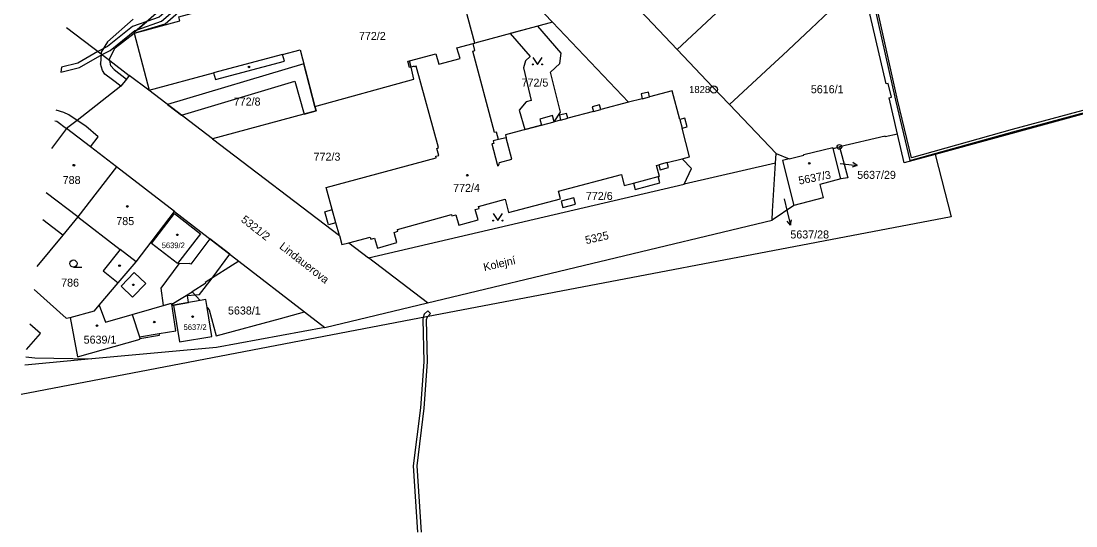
# Model space of a CAD drawing. Extents: x -821458 to -820266, y -1071458 to -1069826.
# Drawn here: x -821428.9 to -821204.8, y -1070135.7 to -1070028.3 of the extents above; entities that cross this region are included whole.
import ezdxf

# ---------------------------------------------------------------- set-up
doc = ezdxf.new("R2010")
doc.units = 0
for name, color, linetype in [('Vrstva 1', 7, 'Continuous'), ('Vrstva 13', 7, 'Continuous'), ('Vrstva 2', 7, 'Continuous'), ('Vrstva 3', 7, 'Continuous'), ('Vrstva 4', 7, 'Continuous'), ('Vrstva 5', 7, 'Continuous'), ('Vrstva 7', 7, 'Continuous'), ('Vrstva 8', 7, 'Continuous')]:
    doc.layers.add(name, color=color, linetype=linetype)

msp = doc.modelspace()

# ---------------------------------------------------------------- linework, layer by layer
at = {"layer": 'Vrstva 1'}
for p, q in [((-821332.49, -1070033), (-821340.69, -1070002.53)), ((-821340.69, -1070002.53), (-821315.99, -1070028.55)), ((-821299.98, -1070023.29), (-821289.45, -1070034.4)), ((-821315.99, -1070028.55), (-821332.49, -1070033)), ((-821299.81, -1070045.6), (-821315.99, -1070028.55)), ((-821404.89, -1070030.92), (-821401.66, -1070043)), ((-821332.84, -1070033.09), (-821332.49, -1070033)), ((-821401.77, -1070043.03), (-821405.9, -1070039.88)), ((-821182.41, -1070042.44), (-821234.69, -1070056.69)), ((-821401.77, -1070043.03), (-821401.66, -1070043)), ((-821388.21, -1070053.38), (-821401.77, -1070043.03)), ((-821268.48, -1070056.5), (-821278.33, -1070046.1)), ((-821388.21, -1070053.38), (-821361.25, -1070073.95)), ((-821256.32, -1070055.41), (-821255.01, -1070055.1)), ((-821254.68, -1070061.91), (-821256.32, -1070055.41)), ((-821268.6, -1070058.51), (-821288.01, -1070063.04)), ((-821268.6, -1070058.51), (-821268.48, -1070056.5)), ((-821268.48, -1070056.5), (-821265.69, -1070057.64)), ((-821408.59, -1070059.33), (-821416.81, -1070069.97)), ((-821396.32, -1070068.8), (-821408.59, -1070059.33)), ((-821355.07, -1070078.67), (-821288.01, -1070063.04)), ((-821396.32, -1070068.8), (-821382.59, -1070079.41)), ((-821264.67, -1070067.57), (-821269.3, -1070070.69)), ((-821416.81, -1070069.97), (-821420.03, -1070073.86)), ((-821342.51, -1070088.26), (-821269.3, -1070070.69)), ((-821420.03, -1070073.86), (-821425.52, -1070080.51)), ((-821359.25, -1070075.48), (-821355.07, -1070078.67)), ((-821342.51, -1070088.26), (-821355.07, -1070078.67)), ((-821382.59, -1070079.41), (-821368.64, -1070090.17)), ((-821392.56, -1070085.88), (-821390.82, -1070087.72)), ((-821364.34, -1070093.49), (-821342.51, -1070088.26)), ((-821368.64, -1070090.17), (-821364.34, -1070093.49))]:
    msp.add_line(p, q, dxfattribs=at)
for points in [[(-821355.04, -1069987.4), (-821361.05, -1069992.64), (-821400.19, -1070026.71), (-821404.92, -1070030.82), (-821404.89, -1070030.92)], [(-821404.89, -1070030.92), (-821402.96, -1070030.39), (-821395.18, -1070028.26), (-821395.4, -1070027.44), (-821385.84, -1070024.9), (-821385.62, -1070025.72), (-821378.18, -1070023.74), (-821378.43, -1070022.94), (-821376.42, -1070022.4), (-821376.21, -1070023.22), (-821371.58, -1070021.98), (-821371.8, -1070021.15), (-821367.67, -1070020.04), (-821369.02, -1070015.05), (-821366.37, -1070014.32), (-821356.12, -1070011.49), (-821354.5, -1070017.79), (-821352.33, -1070017.08), (-821352.03, -1070017.97), (-821351.61, -1070017.83), (-821357.55, -1069995.73), (-821357.82, -1069994.73), (-821358.41, -1069992.32), (-821352.01, -1069990.61)], [(-821289.45, -1070034.4), (-821279.09, -1070024.66), (-821277.81, -1070023.46), (-821265.53, -1070012.14)], [(-821278.33, -1070046.1), (-821268.7, -1070037.11), (-821267.06, -1070035.58), (-821261.06, -1070029.96), (-821258.36, -1070027.44), (-821249.59, -1070019.24)], [(-821242.69, -1070052.35), (-821244.41, -1070044.64), (-821243.95, -1070044.52), (-821244.63, -1070041.59), (-821245.07, -1070041.7), (-821249.48, -1070022.73), (-821248.91, -1070022.58), (-821249.59, -1070019.24)], [(-821419.24, -1070029.7), (-821411.87, -1070035.32), (-821410.92, -1070036.04), (-821410.03, -1070036.72), (-821405.9, -1070039.88)], [(-821346.01, -1070038.12), (-821346.35, -1070038.21), (-821346.71, -1070036.89), (-821346.33, -1070036.78), (-821340.76, -1070035.28), (-821340.11, -1070037.52), (-821335.6, -1070036.3), (-821336.27, -1070034.02), (-821332.84, -1070033.09)], [(-821299.81, -1070045.6), (-821305.72, -1070047.14), (-821305.98, -1070046.14), (-821307.53, -1070046.54), (-821307.27, -1070047.55), (-821312.7, -1070048.98), (-821312.96, -1070047.97), (-821314.5, -1070048.37), (-821314.24, -1070049.38), (-821315.61, -1070049.76), (-821315.97, -1070048.44), (-821318.67, -1070049.16), (-821318.31, -1070050.48), (-821325.96, -1070052.5), (-821325.79, -1070053.13), (-821327.43, -1070053.5), (-821327.84, -1070051.97), (-821328.26, -1070052.06), (-821332.89, -1070034.72), (-821332.49, -1070034.62), (-821332.84, -1070033.09)], [(-821401.66, -1070043), (-821387.99, -1070039.35), (-821387.61, -1070040.77), (-821372.94, -1070036.84), (-821373.32, -1070035.42), (-821369.59, -1070034.43), (-821366.45, -1070046.49)], [(-821289.45, -1070034.4), (-821281.88, -1070042.37), (-821278.5, -1070045.92), (-821278.33, -1070046.1)], [(-821366.45, -1070046.49), (-821345.41, -1070040.66), (-821346.01, -1070038.12)], [(-821361.25, -1070073.95), (-821362, -1070071.2), (-821363.6, -1070071.64), (-821364.36, -1070068.86), (-821362.76, -1070068.42), (-821364.05, -1070063.73), (-821340.69, -1070057.44), (-821340.79, -1070057.08), (-821340.15, -1070056.89), (-821340.56, -1070055.43), (-821340.17, -1070055.22), (-821344.92, -1070037.95), (-821345.35, -1070038.07), (-821345.38, -1070037.95), (-821346.01, -1070038.12)], [(-821405.9, -1070039.88), (-821406.52, -1070040.69), (-821407.66, -1070042.21), (-821416.96, -1070049.45), (-821419.2, -1070051.19)], [(-821288.44, -1070057.59), (-821286.83, -1070057.17), (-821288.43, -1070051.09), (-821287.35, -1070050.79), (-821287.83, -1070049), (-821288.9, -1070049.28), (-821290.51, -1070043.17), (-821295.34, -1070044.45), (-821295.6, -1070043.44), (-821297.15, -1070043.84), (-821296.89, -1070044.84), (-821299.81, -1070045.6)], [(-821366.45, -1070046.49), (-821366.21, -1070047.43), (-821388.21, -1070053.38)], [(-821419.2, -1070051.19), (-821422.42, -1070055.41)], [(-821408.59, -1070059.33), (-821414.1, -1070055.1), (-821419.2, -1070051.19)], [(-821242.69, -1070052.35), (-821245.27, -1070052.96), (-821245.31, -1070052.82), (-821255.01, -1070055.1)], [(-821234.69, -1070056.69), (-821241.23, -1070058.48), (-821242.69, -1070052.35)], [(-821265.69, -1070057.64), (-821262.54, -1070056.84), (-821262.57, -1070056.72), (-821256.38, -1070055.19), (-821256.32, -1070055.41)], [(-821255.01, -1070055.1), (-821253.21, -1070061.68), (-821254.68, -1070061.91)], [(-821234.69, -1070056.69), (-821231.29, -1070069.95), (-821344.25, -1070091.52), (-821428.88, -1070107.69)], [(-821359.25, -1070075.48), (-821354.71, -1070074.27), (-821354.59, -1070074.69), (-821353.76, -1070074.46), (-821353.18, -1070076.58), (-821349.04, -1070075.43), (-821349.64, -1070073.27), (-821348.8, -1070073.03), (-821348.91, -1070072.65), (-821337.42, -1070069.46), (-821337.34, -1070069.75), (-821336.48, -1070069.5), (-821335.89, -1070071.71), (-821331.76, -1070070.56), (-821332.37, -1070068.39), (-821331.58, -1070068.18), (-821331.69, -1070067.79), (-821326.04, -1070066.21), (-821325.31, -1070069), (-821314.25, -1070066.12), (-821314.67, -1070064.51), (-821301.34, -1070060.97), (-821300.74, -1070063.29), (-821298.74, -1070062.77), (-821298.41, -1070064.11), (-821293.14, -1070062.74), (-821293.49, -1070061.41), (-821293.25, -1070061.35), (-821293.88, -1070059.02), (-821293.36, -1070058.88), (-821293.08, -1070059.95), (-821291.3, -1070059.48), (-821291.58, -1070058.41), (-821288.44, -1070057.59)], [(-821288.01, -1070063.04), (-821286.46, -1070059.67), (-821288.44, -1070057.59)], [(-821269.3, -1070070.69), (-821269.19, -1070068.76), (-821268.6, -1070058.51)], [(-821265.69, -1070057.64), (-821267.13, -1070058), (-821264.67, -1070067.57)], [(-821254.68, -1070061.91), (-821259.17, -1070063.06), (-821258.49, -1070065.94), (-821264.67, -1070067.57)], [(-821408.29, -1070084.01), (-821404.46, -1070079.49), (-821396.32, -1070068.8)], [(-821390.78, -1070073.56), (-821395.65, -1070079.9), (-821401.2, -1070075.6), (-821396.29, -1070069.25), (-821390.78, -1070073.56)], [(-821420.03, -1070073.86), (-821424.29, -1070070.56)], [(-821416.81, -1070069.97), (-821407.84, -1070076.88), (-821411.44, -1070081.43), (-821408.29, -1070084.01)], [(-821361.25, -1070073.95), (-821360.73, -1070075.84), (-821359.25, -1070075.48)], [(-821382.59, -1070079.41), (-821389.77, -1070083.88), (-821389.64, -1070084.09), (-821392.56, -1070085.88)], [(-821426.13, -1070085.41), (-821419.3, -1070091.5), (-821418.49, -1070091.38)], [(-821418.49, -1070091.38), (-821413.3, -1070089.92), (-821412.27, -1070088.7), (-821408.29, -1070084.01)], [(-821418.49, -1070091.38), (-821416.93, -1070099.75), (-821403.58, -1070095.99), (-821403.65, -1070095.8), (-821399.49, -1070095.09), (-821399.55, -1070094.77), (-821395.97, -1070094.16), (-821396.86, -1070088.51), (-821392.56, -1070085.88)], [(-821389.37, -1070089.24), (-821389.66, -1070087.52), (-821390.82, -1070087.72)], [(-821390.82, -1070087.72), (-821396.53, -1070088.71), (-821395.25, -1070096.54), (-821388.35, -1070095.41), (-821389.37, -1070089.24)], [(-821389.37, -1070089.24), (-821388.9, -1070089.74), (-821387.42, -1070095.23), (-821373.76, -1070091.55), (-821368.64, -1070090.17)], [(-821427.7, -1070098.14), (-821424.78, -1070094.75), (-821427.04, -1070092.8)], [(-821364.34, -1070093.49), (-821387.38, -1070097.71), (-821413.86, -1070100.14)], [(-821413.86, -1070100.14), (-821428.12, -1070101.5)], [(-821427.9, -1070099.74), (-821425.97, -1070099.92), (-821413.86, -1070100.14)]]:
    msp.add_lwpolyline(points, dxfattribs=at)
at = {"layer": 'Vrstva 13'}
msp.add_line((-821420.29, -1070038.16), (-821420.42, -1070039.23), dxfattribs=at)
for points in [[(-821402.16, -1070028.42), (-821404.2, -1070030.19), (-821399.03, -1070028.39), (-821375.58, -1070008.2), (-821359.27, -1069993.93), (-821358.62, -1069991.13), (-821355.66, -1069988.52), (-821354.95, -1069987.5), (-821355.04, -1069987.4), (-821359.73, -1069991.49), (-821360.17, -1069993.39), (-821376.24, -1070007.44), (-821399.53, -1070027.51)], [(-821323.06, -1070047.28), (-821321.86, -1070051.42), (-821318.31, -1070050.48), (-821315.61, -1070049.76), (-821314.26, -1070047.73), (-821316.4, -1070039.21), (-821314.39, -1070037.38), (-821314.12, -1070035.13), (-821319.11, -1070029.39), (-821324.98, -1070030.97), (-821320.71, -1070035.85), (-821321.7, -1070036.76), (-821322.16, -1070038.25), (-821320.5, -1070045.2), (-821321.55, -1070045.5)], [(-821368.71, -1070048.11), (-821366.21, -1070047.43), (-821366.45, -1070046.49), (-821368.81, -1070037.42), (-821397.74, -1070046.1), (-821394.8, -1070048.35), (-821370.71, -1070041.12)], [(-821399.22, -1070085.14), (-821398.68, -1070088.82), (-821396.89, -1070088.31), (-821396.86, -1070088.51), (-821396.82, -1070088.76), (-821396.53, -1070088.71), (-821393.31, -1070088.15), (-821393.53, -1070086.71), (-821391.91, -1070086.56), (-821390.95, -1070086.48), (-821388.31, -1070082.97), (-821384.51, -1070077.92), (-821388.79, -1070074.62), (-821392.84, -1070080.02), (-821393.07, -1070079.84), (-821395.38, -1070079.97)]]:
    msp.add_lwpolyline(points, close=True, dxfattribs=at)
for points in [[(-821249.04, -1070018.55), (-821243.11, -1070045.18), (-821240.07, -1070058), (-821218.16, -1070051.88), (-821163.45, -1070037.13)], [(-821164.06, -1070036.77), (-821218.3, -1070051.4), (-821239.71, -1070057.38), (-821242.63, -1070045.06), (-821248.6, -1070018.25)], [(-821420.42, -1070039.23), (-821416.48, -1070038.22), (-821411.67, -1070035.47), (-821409.95, -1070034.56), (-821404.69, -1070030.36), (-821404.2, -1070030.19), (-821402.16, -1070028.42), (-821405.19, -1070029.48), (-821410.49, -1070033.72), (-821412.55, -1070034.8), (-821416.86, -1070037.28), (-821420.29, -1070038.16)], [(-821343.83, -1070137.02), (-821344.74, -1070122.88), (-821343.24, -1070110.64), (-821342.51, -1070100.79), (-821342.74, -1070091.8), (-821342.55, -1070091.2), (-821341.89, -1070090.53), (-821342.43, -1070089.93), (-821343.22, -1070090.66), (-821343.44, -1070091.37), (-821343.54, -1070091.68), (-821343.31, -1070100.77), (-821344.04, -1070110.56), (-821345.54, -1070122.86), (-821344.63, -1070137.02)]]:
    msp.add_lwpolyline(points, dxfattribs=at)
at = {"layer": 'Vrstva 3'}
msp.add_line((-821417.75, -1070080.63), (-821416, -1070080.63), dxfattribs=at)
for points in [[(-821320.17, -1070036.06), (-821319.17, -1070037.56), (-821318.17, -1070036.06)], [(-821328.58, -1070069.24), (-821327.58, -1070070.74), (-821326.58, -1070069.24)]]:
    msp.add_lwpolyline(points, dxfattribs=at)
for centre, radius in [((-821320.17, -1070037.56), 0.1), ((-821318.17, -1070037.56), 0.1), ((-821328.58, -1070070.74), 0.1), ((-821326.58, -1070070.74), 0.1), ((-821417.75, -1070079.88), 0.75)]:
    msp.add_circle(centre, radius, dxfattribs=at)
at = {"layer": 'Vrstva 4'}
for p, q in [((-821411.87, -1070035.32), (-821412.02, -1070037.4)), ((-821373.32, -1070035.42), (-821387.99, -1070039.35)), ((-821409.82, -1070037.86), (-821410.03, -1070036.72)), ((-821409.82, -1070037.86), (-821409.12, -1070038.65)), ((-821346.01, -1070038.12), (-821346.33, -1070036.78)), ((-821409.12, -1070038.65), (-821406.52, -1070040.69)), ((-821296.89, -1070044.84), (-821295.34, -1070044.45)), ((-821307.27, -1070047.55), (-821305.72, -1070047.14)), ((-821314.24, -1070049.38), (-821312.7, -1070048.98)), ((-821288.9, -1070049.28), (-821288.43, -1070051.09)), ((-821318.31, -1070050.48), (-821315.61, -1070049.76)), ((-821327.43, -1070053.5), (-821328.61, -1070053.82)), ((-821328.61, -1070053.82), (-821328.47, -1070054.33)), ((-821324.59, -1070057.7), (-821325.79, -1070053.13)), ((-821328.47, -1070054.33), (-821328.88, -1070054.44)), ((-821328.88, -1070054.44), (-821327.72, -1070058.79)), ((-821327.32, -1070058.7), (-821327.22, -1070058.41)), ((-821327.22, -1070058.41), (-821324.59, -1070057.7)), ((-821291.58, -1070058.41), (-821293.36, -1070058.88)), ((-821327.72, -1070058.79), (-821327.64, -1070059.1)), ((-821327.64, -1070059.1), (-821327.42, -1070059.01)), ((-821327.42, -1070059.01), (-821327.32, -1070058.7)), ((-821298.74, -1070062.77), (-821293.49, -1070061.41)), ((-821416.81, -1070069.97), (-821423.59, -1070064.86)), ((-821311.43, -1070065.92), (-821314.13, -1070066.61)), ((-821314.13, -1070066.61), (-821313.76, -1070067.95)), ((-821313.76, -1070067.95), (-821311.08, -1070067.25)), ((-821311.08, -1070067.25), (-821311.43, -1070065.92)), ((-821362, -1070071.2), (-821362.76, -1070068.42)), ((-821404.46, -1070079.49), (-821407.84, -1070076.88)), ((-821407.6, -1070084.69), (-821404.83, -1070081.78)), ((-821404.83, -1070081.78), (-821402.41, -1070084.1)), ((-821405.21, -1070087.05), (-821407.6, -1070084.69)), ((-821402.41, -1070084.1), (-821405.21, -1070087.05)), ((-821412.27, -1070088.7), (-821410.95, -1070092.35)), ((-821405.28, -1070090.72), (-821396.89, -1070088.31)), ((-821396.89, -1070088.31), (-821396.86, -1070088.51)), ((-821410.95, -1070092.35), (-821405.28, -1070090.72)), ((-821405.28, -1070090.72), (-821403.74, -1070095.49)), ((-821403.74, -1070095.49), (-821399.55, -1070094.77)), ((-821403.74, -1070095.49), (-821403.65, -1070095.8))]:
    msp.add_line(p, q, dxfattribs=at)
for points in [[(-821404.89, -1070030.92), (-821398.27, -1070028.95), (-821393.72, -1070024.99), (-821386.56, -1070018.77), (-821378.62, -1070011.87)], [(-821405.05, -1070027.96), (-821410.53, -1070032.73), (-821411.84, -1070034.93), (-821411.87, -1070035.32)], [(-821410.03, -1070036.72), (-821410.09, -1070036.35), (-821408.9, -1070034.06), (-821404.89, -1070030.92)], [(-821407.66, -1070042.21), (-821409.48, -1070040.84), (-821411.1, -1070039.63), (-821411.6, -1070038.85), (-821412.02, -1070037.4)], [(-821416.96, -1070049.45), (-821418.73, -1070048.24), (-821419.77, -1070047.77), (-821421.41, -1070047.25)], [(-821421.69, -1070049.51), (-821421.28, -1070049.6), (-821419.2, -1070051.19)], [(-821414.1, -1070055.1), (-821412.49, -1070052.94), (-821415.16, -1070050.68), (-821416.96, -1070049.45)]]:
    msp.add_lwpolyline(points, dxfattribs=at)
at = {"layer": 'Vrstva 5'}
for centre in [(-821380.47, -1070038.09), (-821261.41, -1070058.57), (-821417.66, -1070058.98), (-821334.07, -1070061.11), (-821406.31, -1070067.75), (-821395.68, -1070073.78), (-821407.97, -1070080.33), (-821405.03, -1070084.41), (-821400.58, -1070092.32), (-821392.44, -1070091.17), (-821412.74, -1070093.08)]:
    msp.add_circle(centre, 0.175, dxfattribs=at)
at = {"layer": 'Vrstva 7'}
for p, q in [((-821251.22, -1070059.03), (-821252.17, -1070058.43)), ((-821254.83, -1070058.65), (-821254.21, -1070058.72)), ((-821254.21, -1070058.72), (-821251.22, -1070059.03)), ((-821251.22, -1070059.03), (-821252.27, -1070059.43)), ((-821266.78, -1070066.14), (-821266.14, -1070068.8)), ((-821266.14, -1070068.8), (-821265.41, -1070071.71)), ((-821265.41, -1070071.71), (-821266.14, -1070070.86)), ((-821265.41, -1070071.71), (-821265.17, -1070070.62))]:
    msp.add_line(p, q, dxfattribs=at)
at = {"layer": 'Vrstva 8'}
for centre, radius in [((-821281.69, -1070042.88), 0.75), ((-821281.69, -1070042.88), 0.03), ((-821255.01, -1070055.1), 0.5), ((-821255.01, -1070055.1), 0.0303)]:
    msp.add_circle(centre, radius, dxfattribs=at)

# ---------------------------------------------------------------- texts
at = {"layer": 'Vrstva 2'}
for s, height, p in [('772/2', 1.7, (-821357.09, -1070032.35)), ('772/5', 1.7, (-821322.54, -1070042.27)), ('5616/1', 1.7, (-821261.08, -1070043.68)), ('772/8', 1.7, (-821383.7, -1070046.3)), ('772/3', 1.7, (-821366.73, -1070058.01)), ('5637/29', 1.7, (-821251.23, -1070061.88)), ('788', 1.7, (-821420.04, -1070062.97)), ('772/4', 1.7, (-821337.08, -1070064.65)), ('772/6', 1.7, (-821308.87, -1070066.36)), ('785', 1.7, (-821408.65, -1070071.71)), ('5637/28', 1.7, (-821265.43, -1070074.55)), ('5639/2', 1.2, (-821399, -1070076.61)), ('786', 1.7, (-821420.37, -1070084.79)), ('5638/1', 1.7, (-821384.92, -1070090.72)), ('5637/2', 1.2, (-821394.36, -1070094.01)), ('5639/1', 1.7, (-821415.59, -1070096.91))]:
    msp.add_text(s, height=height, dxfattribs=at).set_placement(p)
for s, rotation, p in [('5637/3', 11, (-821263.53, -1070063.11)), ('5321/2', 322, (-821382.3, -1070070.84)), ('5325', 13, (-821308.81, -1070075.78))]:
    msp.add_text(s, height=1.7, rotation=rotation, dxfattribs=at).set_placement(p)
at = {"layer": 'Vrstva 7'}
for s, rotation, p in [('Lindauerova', 322, (-821374.14, -1070076.54)), ('Kolejní', 13, (-821330.44, -1070081.51))]:
    msp.add_text(s, height=1.7, rotation=rotation, dxfattribs=at).set_placement(p)
at = {"layer": 'Vrstva 8'}
msp.add_text('1828', height=1.5, dxfattribs=at).set_placement((-821286.94, -1070043.63))

doc.saveas('drawing.dxf')
